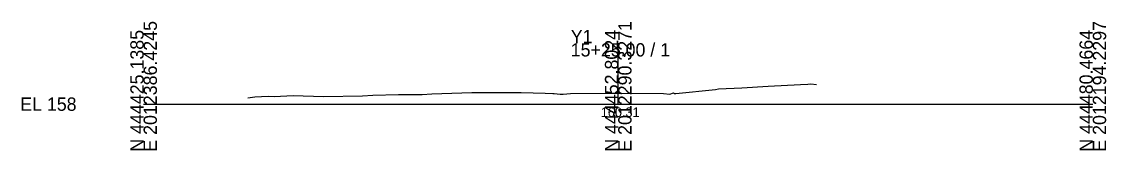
# Model space of a CAD drawing. Extents: x -26 to 3203, y -10 to 9517.
# Drawn here: x 974.3 to 1202.8, y 490.3 to 517.3 of the extents above; entities that cross this region are included whole.
import ezdxf

# ---------------------------------------------------------------- set-up
doc = ezdxf.new("R2010")
doc.units = 0
for name, color, linetype in [('Default', 7, 'Continuous'), ('Exist Cross Section Cell', 7, 'Continuous'), ('Exist XS Center Line Elevation Label', 7, 'Continuous'), ('Exist XS Ground Line', 7, 'Continuous')]:
    doc.layers.add(name, color=color, linetype=linetype)

msp = doc.modelspace()

# ---------------------------------------------------------------- linework, layer by layer
at = {"layer": 'Exist Cross Section Cell'}
for p, q in [((1100, 500), (1100, 512.82)), ((1000, 500), (1100, 500)), ((1100, 500), (1200, 500))]:
    msp.add_line(p, q, dxfattribs=at)
at = {"layer": 'Exist XS Ground Line'}
msp.add_lwpolyline([(1021.98, 501.36), (1023.46, 501.56), (1026.25, 501.68), (1027.5, 501.63), (1031.51, 501.8), (1037.9, 501.63), (1046.12, 501.76), (1048.31, 501.87), (1053.72, 502), (1058.72, 502.06), (1060.73, 502.15), (1069.12, 502.44), (1075.35, 502.48), (1079.53, 502.48), (1084.63, 502.3), (1086.23, 502.27), (1086.53, 502.24), (1087.75, 502.1), (1088.4, 502.13), (1089.93, 502.25), (1098.06, 502.33), (1099.43, 502.32), (1100.19, 502.31), (1100.68, 502.29), (1109.51, 502.26), (1110.88, 502.1), (1111.63, 502.41), (1111.79, 502.22), (1112.15, 502.27), (1120.47, 503.11), (1121.15, 503.21), (1126.02, 503.45), (1131.56, 503.76), (1138.4, 504.12), (1139.96, 504.2), (1140.57, 504.27), (1141.8, 504.13)], dxfattribs=at)

# ---------------------------------------------------------------- texts
at = {"layer": 'Default'}
msp.add_text('-', height=0.0001, dxfattribs=at).set_placement((1000, 500))
at = {"layer": 'Exist Cross Section Cell'}
for s, p in [('E 2012386.4245', (1002.8, 490)), ('E 2012290.3271', (1102.8, 490)), ('E 2012194.2297', (1202.8, 490)), ('N 444425.1385', (1000, 490)), ('N 444452.8024', (1100, 490)), ('N 444480.4664', (1200, 490))]:
    msp.add_text(s, height=2.8, rotation=90, dxfattribs=at).set_placement(p)
for s, p in [('Y1', (1090, 512.82)), ('15+25.00 / 1', (1090, 510.02)), ('EL 158', (974, 498.6))]:
    msp.add_text(s, height=2.8, dxfattribs=at).set_placement(p)
at = {"layer": 'Exist XS Center Line Elevation Label'}
msp.add_text('160.31', height=2, dxfattribs=at).set_placement((1096.32, 497.31))

doc.saveas('drawing.dxf')
